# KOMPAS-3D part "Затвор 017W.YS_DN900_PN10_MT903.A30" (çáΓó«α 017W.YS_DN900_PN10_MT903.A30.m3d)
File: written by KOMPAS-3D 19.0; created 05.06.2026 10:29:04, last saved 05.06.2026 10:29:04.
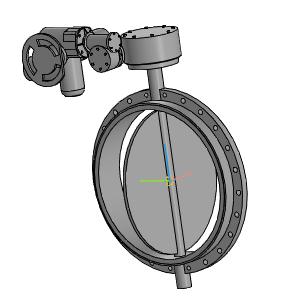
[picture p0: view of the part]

Document properties: Автор: Энергия; Полное имя файла: ..\..\..\3d для проектировщиков\x.x Тип 017W.Y(S) Затвор дисковый поворотный межфланцевый\Затвор 017W.Y(S)_DN32-DN1200_QT.A_MT903.A\Затвор 017W.YS_DN900_PN10_MT903.A30.a3d

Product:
- Part/product: Затвор 017W.YS_DN900_PN10_MT903.A30
    Масса: 727.932

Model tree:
1. Операция без истории:1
